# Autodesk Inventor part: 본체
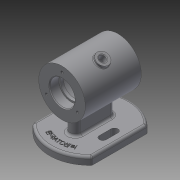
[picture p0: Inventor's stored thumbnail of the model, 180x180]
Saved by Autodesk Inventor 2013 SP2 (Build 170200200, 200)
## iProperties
Created: 2022-02
Part Number: 본체
Material: Generic
Document SubType Name: Modeling
Designer: a
Density: 1 g/cm^3
Mass: 183.432 g
Surface Area: 489.776 cm^2
Volume: 183.432 cm^3
Author: a
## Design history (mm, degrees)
sketch "스케치1"
  geometry: L1 (-36, 0)-(36, 0); L2 (-36, 16)-(-36, 30); L3 (-36, 30)-(36, 30); L4 (36, 30)-(36, 16); L5 (36, 16)-(24, 16); L6 (24, 16)-(24, 14); L7 (24, 14)-(20, 14); L8 (20, 14)-(20, 25); L9 (20, 25)-(-20, 25); L10 (-20, 25)-(-20, 14); L11 (-20, 14)-(-24, 14); L12 (-24, 14)-(-24, 16); L13 (-24, 16)-(-36, 16); 3 further points
  constraints: 26 end point, 9 parallel, 2 midpoint, 2 perpendicular, 1 coincident, 1 collinear, 1 horizontal, 1 vertical, 1 vertical alignment
  dimensions: "d0" = 72 distance of L1.start L1.end; "d1" = 28 diameter of L11 L1; "d2" = 28 diameter of L7 L1; "d3" = 60 diameter of L3 L1; "d4" = 50 diameter of L9 L1; "d5" = 32 diameter of L13 L1; "d6" = 32 diameter of L5 L1; "d7" = 12 distance of L12.end L2.start; "d8" = 40 distance of L8.end L9.end; "d9" = 12 distance of L4.end L5.end; "d10" = 72 distance from line of L4 point (-36, 23)
revolve "회전1" sketch "스케치1" stored, may be unused: angle "d11" = 90 deg
node "작업 평면1"
sketch "스케치2"
  geometry: L1 (36, 30)-(36, -30) reference; L2 (-36, 30)-(-36, -30) reference; L3 (36, -30)-(-36, -30) reference; L4 (35.496, -38)-(-35.496, -38); L5 (35.496, 38)-(-35.496, 38); A1 r 52 centre (0, 0) between (35.496, -38) and (35.496, 38); A2 r 52 centre (0, 0) between (-35.496, 38) and (-35.496, -38); 1 further point
  constraints: 4 end point, 4 point on circle, 2 centre point, 2 parallel, 1 coincident
  dimensions: "d14" = 76 distance between parallel lines of L5 L4; "d15" = 38 distance from line of L5 point (0, 0); "d16" = 52 radius of A2; "d17" = 52 radius of A1
extrude "돌출1" join sketch "스케치2" distance "d18" = 10; taper "d19" = 0 deg
sketch "스케치3"
  geometry: L1 (-26, -7)-(26, -7); L2 (26, -7)-(26, 7); L3 (26, 7)-(-26, 7); L4 (-26, 7)-(-26, -7); L5 (-26, -7)-(26, 7); L6 (26, -7)-(-26, 7); L7 (12, 19.5)-(-12, 19.5); L8 (-12, 19.5)-(-12, 28.5); L9 (-12, 28.5)-(12, 28.5); L10 (12, 28.5)-(12, 19.5); L11 (12, 19.5)-(-12, 28.5); L12 (-12, 19.5)-(12, 28.5); A1 r 52 centre (0, 0) between (-35.496, 38) and (-35.496, -38) reference; A2 r 52 centre (0, 0) between (35.496, -38) and (35.496, 38) reference; 5 further points
  constraints: 24 end point, 8 midpoint, 4 parallel, 2 horizontal, 2 perpendicular, 2 vertical alignment
  dimensions: "d20" = 52 distance of L3.end L2.end; "d21" = 14 distance of L2.end L1.end; "d22" = 24 distance of L8.end L9.end; "d23" = 9 distance of L7.end L8.end; "d24" = 24 distance of A1.centre point (0, 24)
extrude "돌출2" join sketch "스케치3" stored distance "d25" = 10; taper "d26" = 0 deg
extrude "돌출3" cut sketch "스케치3" stored distance "d27" = 10; taper "d28" = 0 deg
fillet "모깎기1" dims "d29" = 4.5
sketch "스케치4"
  geometry: L1 (0, 0)-(28.579, 16.5); L2 (0, 0)-(33, 0); 1 further point
  constraints: 4 end point, 1 coincident, 1 equal length, 1 horizontal
  dimensions: "d30" = 33 distance of L1.start L1.end; "d31" = 30 deg angle of L2 L1
node "작업 평면2"
sketch "스케치5"
  geometry: C1 r 8 at (0, 0); 1 further point
  constraints: 1 centre point, 1 coincident
  dimensions: "d32" = 16 diameter of C1
extrude "돌출4" join sketch "스케치5" stored distance "d34" = 10; taper "d35" = 0 deg
sketch "스케치6"
  geometry: C1 r 8 at (0, 0) reference; 1 further point
  constraints: 1 coincident
hole "구멍1" sketch "스케치6" at (0, 0) diameter "d36" = 8; stored, may be unused: countersink angle "d40" = 90 deg, drill point angle "d42" = 118 deg; dims "d37" = 6, "d38" = 4, "d39" = 2, "d41" = 8
sketch "스케치7"
  geometry: C1 r 30 at (0, 0) reference; 1 further point
  dimensions: "d43" = 23 distance of C1.centre point (0, 23)
hole "구멍2" sketch "스케치7" at (0, 23) diameter "d44" = 3.242; stored, may be unused: countersink angle "d48" = 90 deg, drill point angle "d50" = 118 deg; dims "d45" = 8, "d46" = 4, "d47" = 2, "d49" = 10
sketch "스케치8"
  geometry: C1 r 42.5 at (0, 0); A1 r 52 centre (0, 0) between (35.496, -38) and (35.496, 38) reference
  constraints: 1 centre point, 1 coincident, 1 other
  dimensions: "d54" = 85 diameter of C1
feature "엠보싱1" sketch "스케치8" dims "d55" = 0.5, "d56" = 0
fillet "모깎기2" dims "d57" = 0.3, "d58" = 3
chamfer "모따기1" distance "d59" = 1; stored, may be unused: second distance "d60" = 2, angle "d61" = 45 deg
fillet "모깎기3" dims "d65" = 7
fillet "모깎기4" dims "d66" = 3
fillet "모깎기5" dims "d67" = 3
fillet "모깎기6" dims "d68" = 3
fillet "모깎기7" dims "d69" = 1
fillet "모깎기8" dims "d70" = 1
node "솔리드1"
mirror "대칭1"
pattern_circular "원형 패턴1" dims angle "d52" = 360 deg
mirror "대칭2"
other parameters: "d12" = -62, "d13" = 104
